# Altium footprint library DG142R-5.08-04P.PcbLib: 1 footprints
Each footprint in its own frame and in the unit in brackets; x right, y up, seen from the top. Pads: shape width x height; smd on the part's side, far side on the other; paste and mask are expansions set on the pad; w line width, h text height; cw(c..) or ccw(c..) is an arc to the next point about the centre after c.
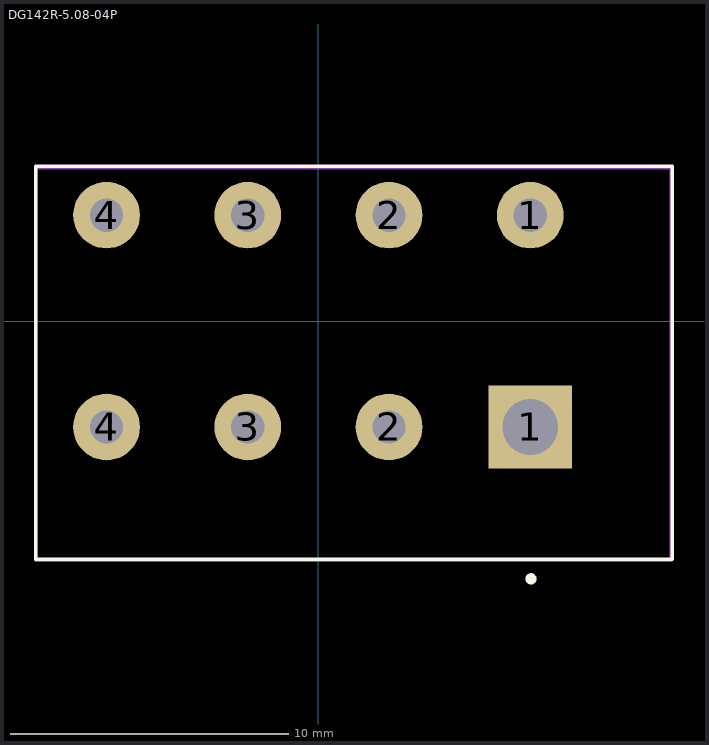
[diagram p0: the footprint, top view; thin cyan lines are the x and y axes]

## DG142R-5.08-04P [mm]
pads (8):
  rect 3x3 hole 2: 1(7.62,-3.81)
  round 2.4 hole 1.2: 1(7.62,3.81) 2(2.54,-3.81) 2(2.54,3.81) 3(-2.54,-3.81) 3(-2.54,3.81) 4(-7.62,-3.81) 4(-7.62,3.81)
Top Overlay:
  circle w0.2: c7.645,-9.271 r0.1
  lines w0.127: -10.16,-8.56 -10.16,5.563 12.725,5.563 12.725,-8.56 -10.16,-8.56
Mechanical 13:
  lines w0.127: -10.165,-8.611 12.7,-8.611 12.7,5.512 -10.165,5.512 -10.165,-8.611
3D body "DG142R-5.08-04P.stp": height 13.44, standoff -3.46, extent -10.213,-8.582 12.647,5.521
